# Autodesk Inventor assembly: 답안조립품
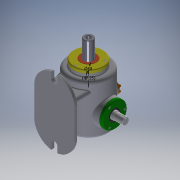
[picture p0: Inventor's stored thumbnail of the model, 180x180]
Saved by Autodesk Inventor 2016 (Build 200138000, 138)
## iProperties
Created: 2018-02
Part Number: 답안조립품
Material: 일반
Document SubType Name: Assembly
Designer: 605-04
Author: 605-04
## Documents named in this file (16)
- C:\Users\605-04\Desktop\380207V1016\답안조립품.iam
- C:\Users\605-04\Desktop\380207V1016\본체.ipt
- C:\Users\605-04\Desktop\380207V1016\가변스프링.ipt
- C:\Users\605-04\Desktop\380207V1016\베어링 6205.ipt
- 베어링 6205.ipt
- C:\Users\605-04\Desktop\380207V1016\본체커버.ipt
- C:\Users\605-04\Desktop\380207V1016\볼트 M4.ipt
- C:\Users\605-04\Desktop\380207V1016\부시.ipt
- C:\Users\605-04\Desktop\380207V1016\상부 캡.ipt
- C:\Users\605-04\Desktop\380207V1016\슬라이드 커버.ipt
- C:\Users\605-04\Desktop\380207V1016\슬라이드.ipt
- C:\Users\605-04\Desktop\380207V1016\오일실.ipt
- 오일실.ipt
- C:\Users\605-04\Desktop\380207V1016\축 커버-1.ipt
- C:\Users\605-04\Desktop\380207V1016\축 커버-2.ipt
- C:\Users\605-04\Desktop\380207V1016\편심축.ipt
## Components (1 placed, 1 different names)
1. 가변스프링:1
